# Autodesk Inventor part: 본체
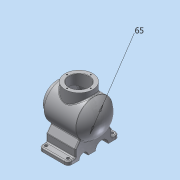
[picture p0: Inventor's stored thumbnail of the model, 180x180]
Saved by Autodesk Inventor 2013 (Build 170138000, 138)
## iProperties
Created: 2018-08
Part Number: 본체
Material: 알루미늄 6061
Document SubType Name: Modeling
Designer: dgall
Density: 2.71 g/cm^3
Mass: 1888.41 g
Surface Area: 1033.26 cm^2
Volume: 696.829 cm^3
Author: dgall
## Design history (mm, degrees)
sketch "스케치1"
  geometry: L1 (0, 0)-(130, 0); L2 (0, 0)-(0, 38); L3 (0, 38)-(12, 38); L4 (12, 38)-(12, 50); L5 (12, 50)-(101.394, 50); A1 r 58 centre (72, 0) between (130, 0) and (101.394, 50); 1 further point; 1 other entity
  constraints: 11 end point, 3 perpendicular, 2 point on circle, 1 centre point, 1 coincident, 1 horizontal, 1 point on line, 1 vertical, 2 other
  dimensions: "d1" = 76 diameter of L3 L1; "d12" = 12 distance between parallel lines of L4 L2; "d77" = 116 diameter of A1; "d80" = 100 diameter of L5 L1; "d109" = 60 distance from line of A1.centre L4
revolve "회전1" sketch "스케치1" stored, may be unused: angle "d11" = 90 deg
sketch "스케치3"
  geometry: L1 (0, 0)-(120, 0); L2 (0, 0)-(0, 27); L3 (0, -38)-(0, 38) reference; L4 (0, 0)-(0, 13.875); L5 (0, 27)-(22, 27); L6 (22, 27)-(22, 37); L7 (101.394, -50)-(101.394, 50) reference; L8 (12, -50)-(12, 50) reference; L9 (25, 40)-(98.533, 40); A1 r 3 centre (25, 37) between (25, 40) and (22, 37); A2 r 58 centre (72, 0) between (101.394, -50) and (101.394, 50) reference; A3 r 48 centre (72, 0) between (120, 0) and (98.533, 40); 1 further point
  constraints: 12 end point, 4 point on circle, 3 perpendicular, 2 centre point, 2 point on line, 2 tangent, 1 horizontal
  dimensions: "d20" = 3 radius of A1; "d82" = 10 radial gap between concentric circles of A2 A3; "d83" = 54 diameter of L5 L1; "d100" = 80 diameter of L9 L1; "d142" = 22 distance between parallel lines of L6 L3
  node "투영된 루프1"
fillet "모깎기1" dims "d25" = 3
fillet "모깎기2" dims "d26" = 3
sketch "스케치4" dims "d27" = 65
  geometry: L1 (0, 0)-(32.5, 0); 1 further point
  constraints: 2 end point, 2 horizontal alignment, 1 coincident, 1 horizontal, 2 other
hole "구멍1" sketch "스케치4" at (32.5, 0) diameter "d30" = 3.242; stored, may be unused: countersink angle "d34" = 82 deg, drill point angle "d36" = 118 deg; dims "d31" = 8, "d32" = 3.023, "d33" = 2, "d35" = 10
node "작업 평면1"
sketch "스케치5"
  geometry: L1 (100, 70)-(20, 70); L2 (20, 70)-(20, -70); L3 (20, -70)-(100, -70); L4 (100, -70)-(100, 70); L5 (12, -47)-(12, 47) reference; 1 further point
  constraints: 8 end point, 2 parallel, 1 horizontal, 1 perpendicular
  dimensions: "d74" = 8 distance between parallel lines of L5 L2; "d88" = 80 distance between parallel lines of L4 L2; "d89" = 140 distance between parallel lines of L3 L1; "d90" = 70 distance from line of point (0, 0) L1
extrude "돌출1" join sketch "스케치5" distance "d46" = 10; taper "d47" = 0 deg
node "작업 평면2"
sketch "스케치6"
  geometry: L1 (70, -72)-(-70, -72) reference; L2 (-50, -72)-(-50, -52); L3 (-50, -52)-(-36.821, -33.178); L4 (50, -72)-(50, -52); L5 (50, -52)-(36.821, -33.178); L6 (-70, -82)-(-70, -72) reference; L7 (70, -82)-(70, -72) reference; C1 r 50 at (0, 0) reference; A1 r 50 centre (0, 0) between (-37.078, -33.545) and (37.078, -33.545); 1 further point
  constraints: 8 end point, 4 point on line, 2 point on circle, 1 centre point, 1 coincident, 1 concentric, 1 horizontal alignment, 1 parallel, 1 perpendicular
  dimensions: "d49" = 35 deg angle of L6 L3; "d50" = 35 deg angle of L7 L5; "d51" = 20 distance between parallel lines of L7 L4; "d52" = 20 distance between parallel lines of L2 L6; "d53" = 20 distance from line of L1 L2.end
fillet "모깎기3" dims "d66" = 10
sketch "스케치8"
  geometry: C1 r 4 at (90, 60); C2 r 4 at (30, 60); A1 r 10 centre (30, 60) between (30, 70) and (20, 60) reference; A2 r 10 centre (90, 60) between (100, 60) and (90, 70) reference; 1 further point
  constraints: 2 centre point, 2 coincident
  dimensions: "d67" = 8 diameter of C1; "d69" = 8 diameter of C2
extrude "돌출4" cut sketch "스케치8" distance "d70" = 10; taper "d71" = 0 deg
revolve "회전3" stored, may be unused: angle "d84" = 90 deg
extrude "돌출6" join sketch "스케치6" stored distance "d93" = 80; taper "d94" = 0 deg
fillet "모깎기6" dims "d95" = 3
fillet "모깎기7" dims "d96" = 3
fillet "모깎기8" dims "d97" = 3
node "작업 평면3"
sketch "스케치9"
  geometry: C1 r 40 at (0, 0) reference; C2 r 27 at (0, 0) reference; C3 r 32.5 at (0, 0); 1 further point
  constraints: 1 centre point, 1 coincident, 1 other
  dimensions: "d101" = 65 diameter of C3
node "작업 평면4"
sketch "스케치10"
  geometry: C1 r 38 at (60, -0.23); 1 further point
  constraints: 1 centre point
  dimensions: "d104" = 76 diameter of C1; "d106" = 60 horizontal distance of C1.centre point (0, 0)
extrude "돌출7" join sketch "스케치10" stored distance "d107" = 0.5; taper "d108" = 0 deg
sketch "스케치11"
  geometry: C1 r 38 at (0, 0) reference; C2 r 27 at (0, 0); 1 further point
  constraints: 1 centre point, 1 coincident
  dimensions: "d110" = 54 diameter of C2
extrude "돌출8" cut sketch "스케치11" stored distance "d112" = 0.5; taper "d113" = 0 deg
chamfer "모따기2" distance "d114" = 1; stored, may be unused: second distance "d115" = 2, angle "d116" = 45 deg
sketch "스케치12" dims "d117" = 65
  geometry: C1 r 38 at (0, 0) reference; C2 r 28 at (0, 0) reference; 3 further points
  constraints: 2 vertical alignment, 1 coincident, 2 other
hole "구멍2" sketch "스케치12" at (0, 32.5) diameter "d119" = 3.242; stored, may be unused: countersink angle "d123" = 82 deg, drill point angle "d125" = 118 deg; dims "d120" = 8, "d121" = 3.023, "d122" = 2, "d124" = 10
fillet "모깎기9" dims "d129" = 3
chamfer "모따기3" distance "d130" = 1; stored, may be unused: second distance "d131" = 2, angle "d132" = 45 deg
fillet "모깎기10" dims "d133" = 2
fillet "모깎기11" dims "d134" = 3
sketch "스케치13"
  geometry: L1 (0, 0)-(0, 120) reference; C1 r 17.5 at (0, 82.5); C2 r 12.5 at (0, 32.5); A1 r 52.536 centre (-82, 60) between (-44.148, 23.569) and (-44.148, 96.431) reference
  constraints: 2 centre point, 2 point on line
  dimensions: "d135" = 25 diameter of C2; "d137" = 35 diameter of C1; "d138" = 27.5 vertical distance of A1.centre C2.centre; "d139" = 22.5 vertical distance of C1.centre A1.centre
extrude "돌출9" cut sketch "스케치13" stored distance "d140" = 0.5; taper "d141" = 0 deg
node "솔리드1"
mirror "대칭1"
pattern_circular "원형 패턴2" dims angle "d86" = 360 deg
pattern_circular "원형 패턴3" dims angle "d127" = 360 deg
other parameters: "d40" = -82, "d98" = 108, "d103" = 65
